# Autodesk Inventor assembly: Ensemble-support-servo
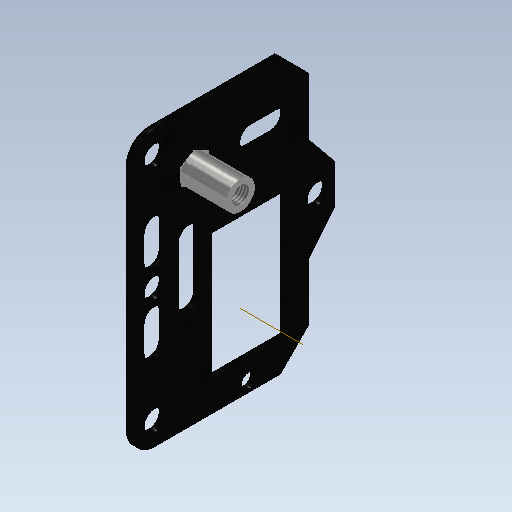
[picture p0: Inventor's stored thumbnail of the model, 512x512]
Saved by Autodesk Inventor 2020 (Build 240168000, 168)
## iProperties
Created: 2021-10
Part Number: Ensemble-support-servo
Document SubType Name: Assembly
Designer: bruno
Author: bruno
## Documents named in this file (3)
- C:\Users\bruno\Documents\1-Cours-2021-22\1SI\Challenge-2021\Pince-Inventor\Ensemble-support-servo.iam
- C:\Users\bruno\Documents\1-Cours-2021-22\1SI\Challenge-2021\Pince-Inventor\support-servo.ipt
- C:\Users\bruno\Documents\1-Cours-2021-22\1SI\Challenge-2021\Pince-Inventor\Ecrou-support.ipt
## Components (2 placed, 2 different names)
1. support-servo:1 — Placage:1, Placage:2, Affleurement:1
2. Ecrou-support:1 — Placage:1, Placage:2, Affleurement:1
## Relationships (3: Mate 2, Flush 1)
- Placage:1 [Mate]: support-servo:1 ↔ Ecrou-support:1
- Placage:2 [Mate]: support-servo:1 ↔ Ecrou-support:1
- Affleurement:1 [Flush]: support-servo:1 ↔ Ecrou-support:1
